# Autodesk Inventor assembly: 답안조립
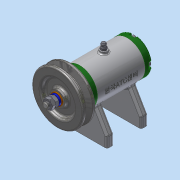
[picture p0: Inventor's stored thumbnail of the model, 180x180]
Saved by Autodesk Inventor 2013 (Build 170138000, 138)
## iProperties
Created: 2018-05
Part Number: 답안조립
Document SubType Name: Assembly
Designer: dgall
Author: dgall
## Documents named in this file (16)
- C:\Users\dgall\Desktop\480507V1011\답안조립.iam
- C:\Users\dgall\Desktop\480507V1011\본체.ipt
- C:\Users\dgall\Desktop\480507V1011\V벨트풀리.ipt
- C:\Users\dgall\Desktop\480507V1011\너트 M8.ipt
- C:\Users\dgall\Desktop\480507V1011\니플 M6x0.75.ipt
- C:\Users\dgall\Desktop\480507V1011\뒤커버.ipt
- C:\Users\dgall\Desktop\480507V1011\베어링 6002.ipt
- C:\Users\dgall\Desktop\480507V1011\볼트 M4x12.ipt
- C:\Users\dgall\Desktop\480507V1011\볼트 M6x8.ipt
- C:\Users\dgall\Desktop\480507V1011\스프링와셔 8.ipt
- C:\Users\dgall\Desktop\480507V1011\앞커버.ipt
- C:\Users\dgall\Desktop\480507V1011\오일 실 15 25 7.ipt
- C:\Users\dgall\Desktop\480507V1011\와셔 6x11.5.ipt
- C:\Users\dgall\Desktop\480507V1011\와셔 8x17.ipt
- C:\Users\dgall\Desktop\480507V1011\축.ipt
- C:\Users\dgall\Desktop\480507V1011\키 3x3x12.ipt
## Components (1 placed, 1 different names)
1. V벨트풀리:1
